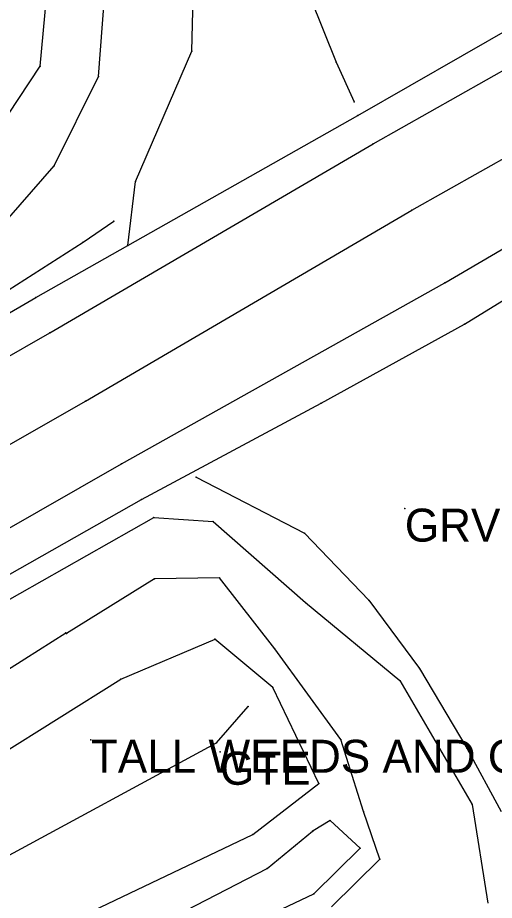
# Model space of a CAD drawing. Extents: x 1419505 to 1434054, y 1956910 to 1968644.
# Drawn here: x 1423094.9 to 1423167.1, y 1958906.3 to 1959040 of the extents above; entities that cross this region are included whole.
import ezdxf

# ---------------------------------------------------------------- set-up
doc = ezdxf.new("R2010")
doc.units = 0
for name, color, linetype in [('S_BREAKLINE', 7, 'Continuous'), ('S_DITCHLINE', 7, 'Continuous'), ('S_DRIVEWAY', 7, 'Continuous'), ('S_EDGE_PAVEMENT', 7, 'Continuous'), ('S_FIBER_OPTIC_CABLE_ANNOT', 7, 'Continuous'), ('S_GRAVEL_ROAD', 7, 'Continuous'), ('S_GRD_PT_SYM', 7, 'Continuous'), ('S_MSC_PT_SYM', 7, 'Continuous'), ('S_PAVEMENT_CROWN', 7, 'Continuous'), ('S_RDW_PT_SYM', 7, 'Continuous'), ('S_SHOULDER', 7, 'Continuous'), ('S_SURVEY_TEXT_ANNOT', 7, 'Continuous'), ('S_UTL_PT_SYM', 7, 'Continuous')]:
    doc.layers.add(name, color=color, linetype=linetype)

msp = doc.modelspace()

# ---------------------------------------------------------------- linework, layer by layer
at = {"layer": 'S_BREAKLINE'}
for p, q in [((1423107.1038, 1959031.1203), (1423108.6809, 1959051.5606)), ((1423098.2853, 1959032.7034), (1423099.9684, 1959051.1316)), ((1423136.3667, 1959050.1775), (1423143.1682, 1959033.2794)), ((1423087.9486, 1959017.0814), (1423098.2853, 1959032.7034)), ((1423143.1682, 1959033.2794), (1423145.8793, 1959027.287)), ((1423100.3844, 1959017.5674), (1423107.1038, 1959031.1203)), ((1423091.1608, 1959006.9957), (1423100.3844, 1959017.5674)), ((1423104.8007, 1959006.0106), (1423109.433, 1959009.2089)), ((1423092.1279, 1958997.9551), (1423104.8007, 1959006.0106)), ((1423063.781, 1958935.0261), (1423115.5304, 1958964.302)), ((1423115.5304, 1958964.302), (1423124.517, 1958963.6929)), ((1423124.517, 1958963.6929), (1423138.5089, 1958951.4171)), ((1423115.5944, 1958954.9724), (1423102.2615, 1958946.7238)), ((1423125.468, 1958955.1374), (1423115.5944, 1958954.9724)), ((1423133.8636, 1958944.3917), (1423125.468, 1958955.1374)), ((1423138.5089, 1958951.4171), (1423152.8188, 1958939.6024)), ((1423080.0141, 1958932.7749), (1423102.1735, 1958946.8168)), ((1423110.5221, 1958939.8134), (1423124.8, 1958945.8318)), ((1423133.5685, 1958938.5073), (1423124.751, 1958945.8378)), ((1423143.8752, 1958930.6368), (1423133.8636, 1958944.3917)), ((1423084.9264, 1958923.7923), (1423110.5221, 1958939.8134)), ((1423152.8188, 1958939.6024), (1423163.7815, 1958920.7901)), ((1423140.536, 1958923.9754), (1423133.5685, 1958938.5073)), ((1423124.996, 1958930.1558), (1423129.8223, 1958935.6321)), ((1423090.3838, 1958911.3985), (1423124.996, 1958930.1558)), ((1423147.3254, 1958919.7241), (1423143.8752, 1958930.6368)), ((1423130.5133, 1958916.2669), (1423140.536, 1958923.9754)), ((1423163.7815, 1958920.7901), (1423166.1336, 1958905.8212)), ((1423149.8016, 1958912.5336), (1423147.3254, 1958919.7241)), ((1423097.4162, 1958900.5028), (1423130.5133, 1958916.2669)), ((1423142.4381, 1958905.2711), (1423149.8016, 1958912.5336))]:
    msp.add_line(p, q, dxfattribs=at)
at = {"layer": 'S_DITCHLINE'}
for p, q in [((1423142.2691, 1958918.36), (1423139.6679, 1958916.7899)), ((1423146.8044, 1958914.1937), (1423142.2691, 1958918.36)), ((1423132.6965, 1958911.1155), (1423139.5879, 1958916.7699)), ((1423139.7569, 1958907.2383), (1423146.8044, 1958914.1937)), ((1423101.6965, 1958895.1015), (1423132.6965, 1958911.1155)), ((1423105.4357, 1958891.1122), (1423139.7569, 1958907.2383))]:
    msp.add_line(p, q, dxfattribs=at)
at = {"layer": 'S_DRIVEWAY'}
for p, q in [((1423121.9198, 1958970.4053), (1423138.3579, 1958961.9098)), ((1423138.3579, 1958961.9098), (1423148.1035, 1958951.7721)), ((1423148.1035, 1958951.7721), (1423155.79, 1958941.4145)), ((1423155.79, 1958941.4145), (1423162.9934, 1958929.3557)), ((1423162.9934, 1958929.3557), (1423168.1588, 1958919.7381))]:
    msp.add_line(p, q, dxfattribs=at)
at = {"layer": 'S_EDGE_PAVEMENT'}
for p, q in [((1423148.7845, 1959020.9336), (1423199.3688, 1959049.5305)), ((1423159.6542, 1958999.8743), (1423206.3462, 1959027.228)), ((1423099.7414, 1958992.2908), (1423148.7845, 1959020.9336)), ((1423110.5951, 1958972.4445), (1423159.6542, 1958999.8743)), ((1423047.602, 1958962.5568), (1423099.7414, 1958992.2908)), ((1423058.3237, 1958942.5015), (1423110.5951, 1958972.4445))]:
    msp.add_line(p, q, dxfattribs=at)
at = {"layer": 'S_GRAVEL_ROAD'}
for p, q in [((1423121.2938, 1959034.9835), (1423121.6938, 1959053.8717)), ((1423112.7382, 1959015.2192), (1423121.2938, 1959034.9835)), ((1423111.5731, 1959005.5216), (1423112.7382, 1959015.2192))]:
    msp.add_line(p, q, dxfattribs=at)
at = {"layer": 'S_GRD_PT_SYM'}
for points in [[(1423098.2853, 1959032.7034), (1423098.2853, 1959032.7534), (1423098.2853, 1959032.7034), (1423098.2353, 1959032.7034), (1423098.2853, 1959032.7034), (1423098.2853, 1959032.6534), (1423098.2853, 1959032.7034), (1423098.3353, 1959032.7034)], [(1423143.1682, 1959033.2794), (1423143.1682, 1959033.3294), (1423143.1682, 1959033.2794), (1423143.1182, 1959033.2794), (1423143.1682, 1959033.2794), (1423143.1682, 1959033.2294), (1423143.1682, 1959033.2794), (1423143.2182, 1959033.2794)], [(1423107.1038, 1959031.1203), (1423107.1038, 1959031.1703), (1423107.1038, 1959031.1203), (1423107.0538, 1959031.1203), (1423107.1038, 1959031.1203), (1423107.1038, 1959031.0703), (1423107.1038, 1959031.1203), (1423107.1538, 1959031.1203)], [(1423145.8793, 1959027.287), (1423145.8793, 1959027.337), (1423145.8793, 1959027.287), (1423145.8293, 1959027.287), (1423145.8793, 1959027.287), (1423145.8793, 1959027.237), (1423145.8793, 1959027.287), (1423145.9293, 1959027.287)], [(1423100.3844, 1959017.5674), (1423100.3844, 1959017.6174), (1423100.3844, 1959017.5674), (1423100.3344, 1959017.5674), (1423100.3844, 1959017.5674), (1423100.3844, 1959017.5174), (1423100.3844, 1959017.5674), (1423100.4344, 1959017.5674)], [(1423109.433, 1959009.2089), (1423109.433, 1959009.2589), (1423109.433, 1959009.2089), (1423109.383, 1959009.2089), (1423109.433, 1959009.2089), (1423109.433, 1959009.1589), (1423109.433, 1959009.2089), (1423109.483, 1959009.2089)], [(1423104.8007, 1959006.0106), (1423104.8007, 1959006.0606), (1423104.8007, 1959006.0106), (1423104.7507, 1959006.0106), (1423104.8007, 1959006.0106), (1423104.8007, 1959005.9606), (1423104.8007, 1959006.0106), (1423104.8507, 1959006.0106)], [(1423115.5304, 1958964.302), (1423115.5304, 1958964.352), (1423115.5304, 1958964.302), (1423115.4804, 1958964.302), (1423115.5304, 1958964.302), (1423115.5304, 1958964.252), (1423115.5304, 1958964.302), (1423115.5804, 1958964.302)], [(1423124.517, 1958963.6929), (1423124.517, 1958963.7429), (1423124.517, 1958963.6929), (1423124.467, 1958963.6929), (1423124.517, 1958963.6929), (1423124.517, 1958963.6429), (1423124.517, 1958963.6929), (1423124.567, 1958963.6929)], [(1423115.5944, 1958954.9724), (1423115.5944, 1958955.0224), (1423115.5944, 1958954.9724), (1423115.5444, 1958954.9724), (1423115.5944, 1958954.9724), (1423115.5944, 1958954.9224), (1423115.5944, 1958954.9724), (1423115.6444, 1958954.9724)], [(1423125.468, 1958955.1374), (1423125.468, 1958955.1874), (1423125.468, 1958955.1374), (1423125.418, 1958955.1374), (1423125.468, 1958955.1374), (1423125.468, 1958955.0874), (1423125.468, 1958955.1374), (1423125.518, 1958955.1374)], [(1423138.5089, 1958951.4171), (1423138.5089, 1958951.4671), (1423138.5089, 1958951.4171), (1423138.4589, 1958951.4171), (1423138.5089, 1958951.4171), (1423138.5089, 1958951.3671), (1423138.5089, 1958951.4171), (1423138.5589, 1958951.4171)], [(1423102.1735, 1958946.8168), (1423102.1735, 1958946.8668), (1423102.1735, 1958946.8168), (1423102.1235, 1958946.8168), (1423102.1735, 1958946.8168), (1423102.1735, 1958946.7668), (1423102.1735, 1958946.8168), (1423102.2235, 1958946.8168)], [(1423102.2615, 1958946.7238), (1423102.2615, 1958946.7738), (1423102.2615, 1958946.7238), (1423102.2115, 1958946.7238), (1423102.2615, 1958946.7238), (1423102.2615, 1958946.6738), (1423102.2615, 1958946.7238), (1423102.3115, 1958946.7238)], [(1423124.751, 1958945.8378), (1423124.751, 1958945.8878), (1423124.751, 1958945.8378), (1423124.701, 1958945.8378), (1423124.751, 1958945.8378), (1423124.751, 1958945.7878), (1423124.751, 1958945.8378), (1423124.801, 1958945.8378)], [(1423124.8, 1958945.8318), (1423124.8, 1958945.8818), (1423124.8, 1958945.8318), (1423124.75, 1958945.8318), (1423124.8, 1958945.8318), (1423124.8, 1958945.7818), (1423124.8, 1958945.8318), (1423124.85, 1958945.8318)], [(1423133.8636, 1958944.3917), (1423133.8636, 1958944.4417), (1423133.8636, 1958944.3917), (1423133.8136, 1958944.3917), (1423133.8636, 1958944.3917), (1423133.8636, 1958944.3417), (1423133.8636, 1958944.3917), (1423133.9136, 1958944.3917)], [(1423110.5221, 1958939.8134), (1423110.5221, 1958939.8634), (1423110.5221, 1958939.8134), (1423110.4721, 1958939.8134), (1423110.5221, 1958939.8134), (1423110.5221, 1958939.7634), (1423110.5221, 1958939.8134), (1423110.5721, 1958939.8134)], [(1423152.8188, 1958939.6024), (1423152.8188, 1958939.6524), (1423152.8188, 1958939.6024), (1423152.7688, 1958939.6024), (1423152.8188, 1958939.6024), (1423152.8188, 1958939.5524), (1423152.8188, 1958939.6024), (1423152.8688, 1958939.6024)], [(1423133.5685, 1958938.5073), (1423133.5685, 1958938.5573), (1423133.5685, 1958938.5073), (1423133.5185, 1958938.5073), (1423133.5685, 1958938.5073), (1423133.5685, 1958938.4573), (1423133.5685, 1958938.5073), (1423133.6185, 1958938.5073)], [(1423129.8223, 1958935.6321), (1423129.8223, 1958935.6821), (1423129.8223, 1958935.6321), (1423129.7723, 1958935.6321), (1423129.8223, 1958935.6321), (1423129.8223, 1958935.5821), (1423129.8223, 1958935.6321), (1423129.8723, 1958935.6321)], [(1423124.996, 1958930.1558), (1423124.996, 1958930.2058), (1423124.996, 1958930.1558), (1423124.946, 1958930.1558), (1423124.996, 1958930.1558), (1423124.996, 1958930.1058), (1423124.996, 1958930.1558), (1423125.046, 1958930.1558)], [(1423143.8752, 1958930.6368), (1423143.8752, 1958930.6868), (1423143.8752, 1958930.6368), (1423143.8252, 1958930.6368), (1423143.8752, 1958930.6368), (1423143.8752, 1958930.5868), (1423143.8752, 1958930.6368), (1423143.9252, 1958930.6368)], [(1423140.536, 1958923.9754), (1423140.536, 1958924.0254), (1423140.536, 1958923.9754), (1423140.486, 1958923.9754), (1423140.536, 1958923.9754), (1423140.536, 1958923.9254), (1423140.536, 1958923.9754), (1423140.586, 1958923.9754)], [(1423163.7815, 1958920.7901), (1423163.7815, 1958920.8401), (1423163.7815, 1958920.7901), (1423163.7315, 1958920.7901), (1423163.7815, 1958920.7901), (1423163.7815, 1958920.7401), (1423163.7815, 1958920.7901), (1423163.8315, 1958920.7901)], [(1423147.3254, 1958919.7241), (1423147.3254, 1958919.7741), (1423147.3254, 1958919.7241), (1423147.2754, 1958919.7241), (1423147.3254, 1958919.7241), (1423147.3254, 1958919.6741), (1423147.3254, 1958919.7241), (1423147.3754, 1958919.7241)], [(1423142.2691, 1958918.36), (1423142.2691, 1958918.41), (1423142.2691, 1958918.36), (1423142.2191, 1958918.36), (1423142.2691, 1958918.36), (1423142.2691, 1958918.31), (1423142.2691, 1958918.36), (1423142.3191, 1958918.36)], [(1423130.5133, 1958916.2669), (1423130.5133, 1958916.3169), (1423130.5133, 1958916.2669), (1423130.4633, 1958916.2669), (1423130.5133, 1958916.2669), (1423130.5133, 1958916.2169), (1423130.5133, 1958916.2669), (1423130.5633, 1958916.2669)], [(1423139.5879, 1958916.7699), (1423139.5879, 1958916.8199), (1423139.5879, 1958916.7699), (1423139.5379, 1958916.7699), (1423139.5879, 1958916.7699), (1423139.5879, 1958916.7199), (1423139.5879, 1958916.7699), (1423139.6379, 1958916.7699)], [(1423139.6679, 1958916.7899), (1423139.6679, 1958916.8399), (1423139.6679, 1958916.7899), (1423139.6179, 1958916.7899), (1423139.6679, 1958916.7899), (1423139.6679, 1958916.7399), (1423139.6679, 1958916.7899), (1423139.7179, 1958916.7899)], [(1423146.8044, 1958914.1937), (1423146.8044, 1958914.2437), (1423146.8044, 1958914.1937), (1423146.7544, 1958914.1937), (1423146.8044, 1958914.1937), (1423146.8044, 1958914.1437), (1423146.8044, 1958914.1937), (1423146.8544, 1958914.1937)], [(1423149.8016, 1958912.5336), (1423149.8016, 1958912.5836), (1423149.8016, 1958912.5336), (1423149.7516, 1958912.5336), (1423149.8016, 1958912.5336), (1423149.8016, 1958912.4836), (1423149.8016, 1958912.5336), (1423149.8516, 1958912.5336)], [(1423132.6965, 1958911.1155), (1423132.6965, 1958911.1655), (1423132.6965, 1958911.1155), (1423132.6465, 1958911.1155), (1423132.6965, 1958911.1155), (1423132.6965, 1958911.0655), (1423132.6965, 1958911.1155), (1423132.7465, 1958911.1155)], [(1423139.7569, 1958907.2383), (1423139.7569, 1958907.2883), (1423139.7569, 1958907.2383), (1423139.7069, 1958907.2383), (1423139.7569, 1958907.2383), (1423139.7569, 1958907.1883), (1423139.7569, 1958907.2383), (1423139.8069, 1958907.2383)]]:
    msp.add_lwpolyline(points, dxfattribs=at)
at = {"layer": 'S_MSC_PT_SYM'}
for points in [[(1423153.5728, 1958965.632), (1423153.5728, 1958965.682), (1423153.5728, 1958965.632), (1423153.5228, 1958965.632), (1423153.5728, 1958965.632), (1423153.5728, 1958965.582), (1423153.5728, 1958965.632), (1423153.6228, 1958965.632)], [(1423105.9678, 1958930.6018), (1423105.9678, 1958930.6518), (1423105.9678, 1958930.6018), (1423105.9178, 1958930.6018), (1423105.9678, 1958930.6018), (1423105.9678, 1958930.5518), (1423105.9678, 1958930.6018), (1423106.0178, 1958930.6018)]]:
    msp.add_lwpolyline(points, dxfattribs=at)
at = {"layer": 'S_PAVEMENT_CROWN'}
for p, q in [((1423154.6389, 1959010.87), (1423203.4401, 1959038.3777)), ((1423105.1427, 1958981.9321), (1423154.6389, 1959010.87)), ((1423052.5453, 1958951.8302), (1423105.1427, 1958981.9321))]:
    msp.add_line(p, q, dxfattribs=at)
at = {"layer": 'S_RDW_PT_SYM'}
for points in [[(1423121.2938, 1959034.9835), (1423121.2938, 1959035.0335), (1423121.2938, 1959034.9835), (1423121.2438, 1959034.9835), (1423121.2938, 1959034.9835), (1423121.2938, 1959034.9335), (1423121.2938, 1959034.9835), (1423121.3438, 1959034.9835)], [(1423146.4394, 1959025.1989), (1423146.4394, 1959025.2489), (1423146.4394, 1959025.1989), (1423146.3894, 1959025.1989), (1423146.4394, 1959025.1989), (1423146.4394, 1959025.1489), (1423146.4394, 1959025.1989), (1423146.4894, 1959025.1989)], [(1423148.7845, 1959020.9336), (1423148.7845, 1959020.9836), (1423148.7845, 1959020.9336), (1423148.7345, 1959020.9336), (1423148.7845, 1959020.9336), (1423148.7845, 1959020.8836), (1423148.7845, 1959020.9336), (1423148.8345, 1959020.9336)], [(1423112.7382, 1959015.2192), (1423112.7382, 1959015.2692), (1423112.7382, 1959015.2192), (1423112.6882, 1959015.2192), (1423112.7382, 1959015.2192), (1423112.7382, 1959015.1692), (1423112.7382, 1959015.2192), (1423112.7882, 1959015.2192)], [(1423154.6389, 1959010.87), (1423154.6389, 1959010.92), (1423154.6389, 1959010.87), (1423154.5889, 1959010.87), (1423154.6389, 1959010.87), (1423154.6389, 1959010.82), (1423154.6389, 1959010.87), (1423154.6889, 1959010.87)], [(1423111.5731, 1959005.5216), (1423111.5731, 1959005.5716), (1423111.5731, 1959005.5216), (1423111.5231, 1959005.5216), (1423111.5731, 1959005.5216), (1423111.5731, 1959005.4716), (1423111.5731, 1959005.5216), (1423111.6231, 1959005.5216)], [(1423159.6542, 1958999.8743), (1423159.6542, 1958999.9243), (1423159.6542, 1958999.8743), (1423159.6042, 1958999.8743), (1423159.6542, 1958999.8743), (1423159.6542, 1958999.8243), (1423159.6542, 1958999.8743), (1423159.7042, 1958999.8743)], [(1423097.6392, 1958997.6061), (1423097.6392, 1958997.6561), (1423097.6392, 1958997.6061), (1423097.5892, 1958997.6061), (1423097.6392, 1958997.6061), (1423097.6392, 1958997.5561), (1423097.6392, 1958997.6061), (1423097.6892, 1958997.6061)], [(1423162.6274, 1958993.5938), (1423162.6274, 1958993.6438), (1423162.6274, 1958993.5938), (1423162.5774, 1958993.5938), (1423162.6274, 1958993.5938), (1423162.6274, 1958993.5438), (1423162.6274, 1958993.5938), (1423162.6774, 1958993.5938)], [(1423099.7414, 1958992.2908), (1423099.7414, 1958992.3408), (1423099.7414, 1958992.2908), (1423099.6914, 1958992.2908), (1423099.7414, 1958992.2908), (1423099.7414, 1958992.2408), (1423099.7414, 1958992.2908), (1423099.7914, 1958992.2908)], [(1423105.1427, 1958981.9321), (1423105.1427, 1958981.9821), (1423105.1427, 1958981.9321), (1423105.0927, 1958981.9321), (1423105.1427, 1958981.9321), (1423105.1427, 1958981.8821), (1423105.1427, 1958981.9321), (1423105.1927, 1958981.9321)], [(1423140.905, 1958981.6311), (1423140.905, 1958981.6811), (1423140.905, 1958981.6311), (1423140.855, 1958981.6311), (1423140.905, 1958981.6311), (1423140.905, 1958981.5811), (1423140.905, 1958981.6311), (1423140.955, 1958981.6311)], [(1423110.5951, 1958972.4445), (1423110.5951, 1958972.4945), (1423110.5951, 1958972.4445), (1423110.5451, 1958972.4445), (1423110.5951, 1958972.4445), (1423110.5951, 1958972.3945), (1423110.5951, 1958972.4445), (1423110.6451, 1958972.4445)], [(1423121.9198, 1958970.4053), (1423121.9198, 1958970.4553), (1423121.9198, 1958970.4053), (1423121.8698, 1958970.4053), (1423121.9198, 1958970.4053), (1423121.9198, 1958970.3553), (1423121.9198, 1958970.4053), (1423121.9698, 1958970.4053)], [(1423113.6603, 1958967.0231), (1423113.6603, 1958967.0731), (1423113.6603, 1958967.0231), (1423113.6103, 1958967.0231), (1423113.6603, 1958967.0231), (1423113.6603, 1958966.9731), (1423113.6603, 1958967.0231), (1423113.7103, 1958967.0231)], [(1423138.3579, 1958961.9098), (1423138.3579, 1958961.9598), (1423138.3579, 1958961.9098), (1423138.3079, 1958961.9098), (1423138.3579, 1958961.9098), (1423138.3579, 1958961.8598), (1423138.3579, 1958961.9098), (1423138.4079, 1958961.9098)], [(1423148.1035, 1958951.7721), (1423148.1035, 1958951.8221), (1423148.1035, 1958951.7721), (1423148.0535, 1958951.7721), (1423148.1035, 1958951.7721), (1423148.1035, 1958951.7221), (1423148.1035, 1958951.7721), (1423148.1535, 1958951.7721)], [(1423155.79, 1958941.4145), (1423155.79, 1958941.4645), (1423155.79, 1958941.4145), (1423155.74, 1958941.4145), (1423155.79, 1958941.4145), (1423155.79, 1958941.3645), (1423155.79, 1958941.4145), (1423155.84, 1958941.4145)], [(1423162.9934, 1958929.3557), (1423162.9934, 1958929.4057), (1423162.9934, 1958929.3557), (1423162.9434, 1958929.3557), (1423162.9934, 1958929.3557), (1423162.9934, 1958929.3057), (1423162.9934, 1958929.3557), (1423163.0434, 1958929.3557)]]:
    msp.add_lwpolyline(points, dxfattribs=at)
at = {"layer": 'S_SHOULDER'}
for p, q in [((1423146.4394, 1959025.1989), (1423179.2455, 1959044.0561)), ((1423097.6392, 1958997.6061), (1423146.4394, 1959025.1989)), ((1423162.6274, 1958993.5938), (1423179.8085, 1959004.2275)), ((1423045.7429, 1958967.8362), (1423097.6392, 1958997.6061)), ((1423140.905, 1958981.6311), (1423162.6274, 1958993.5938)), ((1423113.6603, 1958967.0231), (1423140.905, 1958981.6311)), ((1423061.4729, 1958937.5392), (1423113.6603, 1958967.0231))]:
    msp.add_line(p, q, dxfattribs=at)
at = {"layer": 'S_UTL_PT_SYM'}
msp.add_lwpolyline([(1423125.559, 1958928.7877), (1423125.559, 1958928.8377), (1423125.559, 1958928.7877), (1423125.509, 1958928.7877), (1423125.559, 1958928.7877), (1423125.559, 1958928.7377), (1423125.559, 1958928.7877), (1423125.609, 1958928.7877)], dxfattribs=at)

# ---------------------------------------------------------------- texts
at = {"layer": 'S_FIBER_OPTIC_CABLE_ANNOT'}
msp.add_text('GTE', height=5, dxfattribs=at).set_placement((1423125.559, 1958923.7877))
at = {"layer": 'S_SURVEY_TEXT_ANNOT'}
for s, p in [('GRVL/ASPH NO CU', (1423153.5728, 1958960.632)), ('TALL WEEDS AND GRASS', (1423105.9678, 1958925.6018))]:
    msp.add_text(s, height=5, dxfattribs=at).set_placement(p)

doc.saveas('drawing.dxf')
